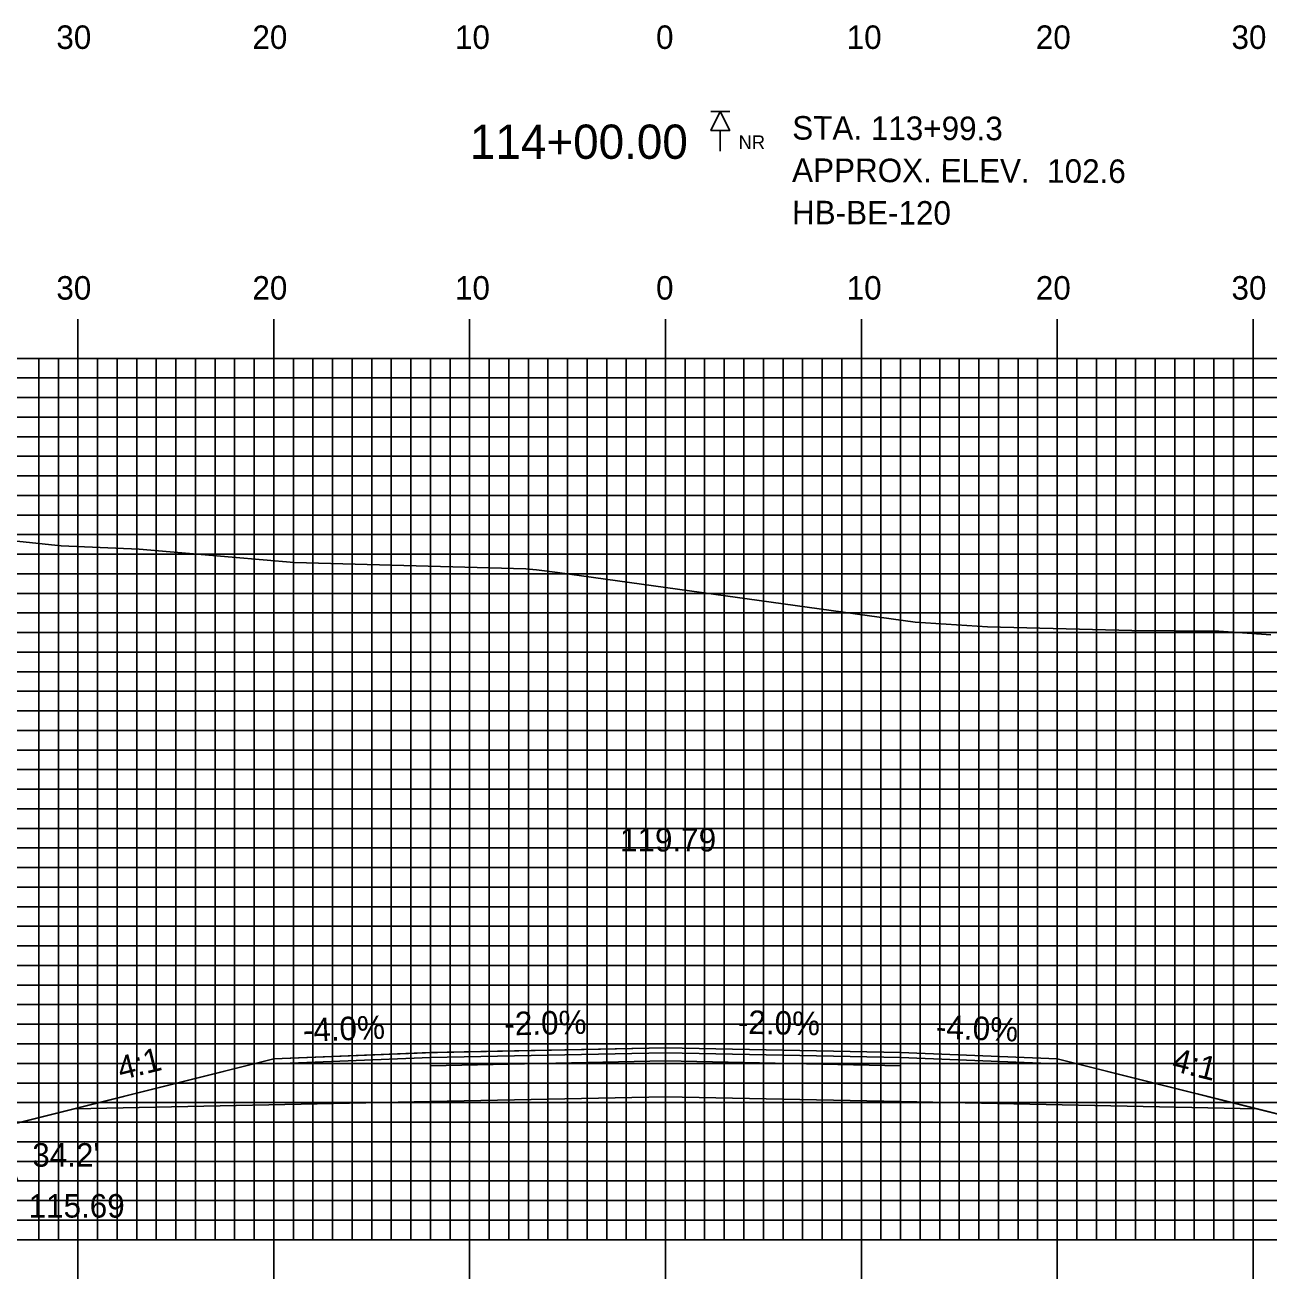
# Model space of a CAD drawing. Extents: x 1770448 to 1770792, y 442591 to 442811.
# Drawn here: x 1770581.3 to 1770644.9, y 442676.7 to 442740.7 of the extents above; entities that cross this region are included whole.
import ezdxf

# ---------------------------------------------------------------- set-up
doc = ezdxf.new("R2010")
doc.units = 0
for name, color, linetype in [('ANNOTATION', 7, 'Continuous'), ('BORING - NO REFUSAL', 7, 'Continuous'), ('D_Roadway_Centerline', 7, 'Continuous'), ('D_Roadway_Centerline_Text', 7, 'Continuous'), ('D_Roadway_Edge_Shoulder', 7, 'Continuous'), ('D_Roadway_Edge_TW', 7, 'Continuous'), ('D_Roadway_Pavement', 7, 'Continuous'), ('D_Roadway_SlopeLines', 7, 'Continuous'), ('D_Roadway_SubGrade', 7, 'Continuous'), ('H_V ANNOTATION', 7, 'Continuous'), ('MAJOR', 7, 'Continuous'), ('MINOR', 7, 'Continuous'), ('S_Roadway_Centerline', 7, 'Continuous')]:
    doc.layers.add(name, color=color, linetype=linetype)

msp = doc.modelspace()

# ---------------------------------------------------------------- linework, layer by layer
at = {"layer": 'ANNOTATION'}
msp.add_lwpolyline([(1770586.666, 442681.667), (1770580.975, 442681.667), (1770579.867, 442684.352)], dxfattribs=at)
at = {"layer": 'BORING - NO REFUSAL'}
for p, q in [((1770617.321, 442736.265), (1770616.361, 442736.265)), ((1770616.841, 442735.306), (1770616.841, 442734.247))]:
    msp.add_line(p, q, dxfattribs=at)
msp.add_lwpolyline([(1770616.841, 442736.265), (1770617.321, 442735.306), (1770616.361, 442735.306)], close=True, dxfattribs=at)
at = {"layer": 'D_Roadway_Centerline'}
msp.add_lwpolyline([(1770520.231, 442717.147), (1770521.481, 442716.994), (1770522.731, 442716.681), (1770523.265, 442716.479), (1770523.981, 442716.207), (1770524.335, 442716.028), (1770525.231, 442715.573), (1770525.235, 442715.571), (1770556.94, 442697.453), (1770579.859, 442684.357), (1770579.867, 442684.352), (1770581.355, 442684.724), (1770583.867, 442685.352), (1770594.041, 442687.896), (1770601.792, 442688.206), (1770602.042, 442688.216), (1770602.398, 442688.223), (1770614.042, 442688.456), (1770626.042, 442688.216), (1770634.041, 442687.896), (1770644.215, 442685.352), (1770646.624, 442684.75)], dxfattribs=at)
at = {"layer": 'D_Roadway_Edge_Shoulder'}
for points in [[(1770602.042, 442688.216), (1770594.041, 442687.896), (1770594.041, 442687.646), (1770602.042, 442687.966)], [(1770626.042, 442688.216), (1770634.041, 442687.896), (1770634.041, 442687.646), (1770626.042, 442687.966)]]:
    msp.add_lwpolyline(points, close=True, dxfattribs=at)
at = {"layer": 'D_Roadway_Edge_TW'}
msp.add_lwpolyline([(1770602.042, 442687.966), (1770602.042, 442688.216), (1770614.042, 442688.456), (1770626.042, 442688.216), (1770626.042, 442687.966), (1770614.042, 442688.206)], close=True, dxfattribs=at)
at = {"layer": 'D_Roadway_Pavement'}
msp.add_lwpolyline([(1770602.042, 442687.549), (1770602.042, 442687.966), (1770614.042, 442688.206), (1770626.042, 442687.966), (1770626.042, 442687.549), (1770614.042, 442687.789)], close=True, dxfattribs=at)
at = {"layer": 'D_Roadway_SlopeLines'}
for points in [[(1770594.041, 442687.896), (1770579.867, 442684.352)], [(1770634.041, 442687.896), (1770648.215, 442684.352)]]:
    msp.add_lwpolyline(points, dxfattribs=at)
at = {"layer": 'D_Roadway_SubGrade'}
msp.add_lwpolyline([(1770602.042, 442685.716), (1770583.867, 442685.352), (1770594.041, 442687.896), (1770594.041, 442687.646), (1770602.042, 442687.966), (1770614.042, 442688.206), (1770626.042, 442687.966), (1770634.041, 442687.646), (1770634.041, 442687.896), (1770644.215, 442685.352), (1770626.042, 442685.716), (1770614.042, 442685.956)], close=True, dxfattribs=at)
at = {"layer": 'MAJOR'}
for p, q in [((1770584.041, 442725.669), (1770584.041, 442723.665)), ((1770594.041, 442725.669), (1770594.041, 442723.665)), ((1770604.041, 442725.669), (1770604.041, 442723.665)), ((1770614.041, 442725.669), (1770614.041, 442723.665)), ((1770624.041, 442725.669), (1770624.041, 442723.665)), ((1770634.041, 442725.669), (1770634.041, 442723.665)), ((1770644.041, 442725.669), (1770644.041, 442723.665)), ((1770474.041, 442723.665), (1770754.041, 442723.665)), ((1770474.041, 442723.665), (1770754.041, 442723.665)), ((1770584.041, 442678.665), (1770584.041, 442723.665)), ((1770594.041, 442678.665), (1770594.041, 442723.665)), ((1770604.041, 442678.665), (1770604.041, 442723.665)), ((1770614.041, 442678.665), (1770614.041, 442723.665)), ((1770624.041, 442678.665), (1770624.041, 442723.665)), ((1770634.041, 442678.665), (1770634.041, 442723.665)), ((1770644.041, 442678.665), (1770644.041, 442723.665)), ((1770474.041, 442718.665), (1770754.041, 442718.665)), ((1770474.041, 442713.665), (1770754.041, 442713.665)), ((1770474.041, 442708.665), (1770754.041, 442708.665)), ((1770474.041, 442703.665), (1770754.041, 442703.665)), ((1770474.041, 442698.665), (1770754.041, 442698.665)), ((1770474.041, 442693.665), (1770754.041, 442693.665)), ((1770474.041, 442688.665), (1770754.041, 442688.665)), ((1770474.041, 442683.665), (1770754.041, 442683.665)), ((1770474.041, 442678.665), (1770754.041, 442678.665)), ((1770474.041, 442678.665), (1770754.041, 442678.665)), ((1770584.041, 442676.661), (1770584.041, 442678.665)), ((1770594.041, 442676.661), (1770594.041, 442678.665)), ((1770604.041, 442676.661), (1770604.041, 442678.665)), ((1770614.041, 442676.661), (1770614.041, 442678.665)), ((1770624.041, 442676.661), (1770624.041, 442678.665)), ((1770634.041, 442676.661), (1770634.041, 442678.665)), ((1770644.041, 442676.661), (1770644.041, 442678.665))]:
    msp.add_line(p, q, dxfattribs=at)
at = {"layer": 'MINOR'}
for p, q in [((1770582.041, 442678.665), (1770582.041, 442723.665)), ((1770583.041, 442678.665), (1770583.041, 442723.665)), ((1770585.041, 442678.665), (1770585.041, 442723.665)), ((1770586.041, 442678.665), (1770586.041, 442723.665)), ((1770587.041, 442678.665), (1770587.041, 442723.665)), ((1770588.041, 442678.665), (1770588.041, 442723.665)), ((1770589.041, 442678.665), (1770589.041, 442723.665)), ((1770590.041, 442678.665), (1770590.041, 442723.665)), ((1770591.041, 442678.665), (1770591.041, 442723.665)), ((1770592.041, 442678.665), (1770592.041, 442723.665)), ((1770593.041, 442678.665), (1770593.041, 442723.665)), ((1770595.041, 442678.665), (1770595.041, 442723.665)), ((1770596.041, 442678.665), (1770596.041, 442723.665)), ((1770597.041, 442678.665), (1770597.041, 442723.665)), ((1770598.041, 442678.665), (1770598.041, 442723.665)), ((1770599.041, 442678.665), (1770599.041, 442723.665)), ((1770600.041, 442678.665), (1770600.041, 442723.665)), ((1770601.041, 442678.665), (1770601.041, 442723.665)), ((1770602.041, 442678.665), (1770602.041, 442723.665)), ((1770603.041, 442678.665), (1770603.041, 442723.665)), ((1770605.041, 442678.665), (1770605.041, 442723.665)), ((1770606.041, 442678.665), (1770606.041, 442723.665)), ((1770607.041, 442678.665), (1770607.041, 442723.665)), ((1770608.041, 442678.665), (1770608.041, 442723.665)), ((1770609.041, 442678.665), (1770609.041, 442723.665)), ((1770610.041, 442678.665), (1770610.041, 442723.665)), ((1770611.041, 442678.665), (1770611.041, 442723.665)), ((1770612.041, 442678.665), (1770612.041, 442723.665)), ((1770613.041, 442678.665), (1770613.041, 442723.665)), ((1770615.041, 442678.665), (1770615.041, 442723.665)), ((1770616.041, 442678.665), (1770616.041, 442723.665)), ((1770617.041, 442678.665), (1770617.041, 442723.665)), ((1770618.041, 442678.665), (1770618.041, 442723.665)), ((1770619.041, 442678.665), (1770619.041, 442723.665)), ((1770620.041, 442678.665), (1770620.041, 442723.665)), ((1770621.041, 442678.665), (1770621.041, 442723.665)), ((1770622.041, 442678.665), (1770622.041, 442723.665)), ((1770623.041, 442678.665), (1770623.041, 442723.665)), ((1770625.041, 442678.665), (1770625.041, 442723.665)), ((1770626.041, 442678.665), (1770626.041, 442723.665)), ((1770627.041, 442678.665), (1770627.041, 442723.665)), ((1770628.041, 442678.665), (1770628.041, 442723.665)), ((1770629.041, 442678.665), (1770629.041, 442723.665)), ((1770630.041, 442678.665), (1770630.041, 442723.665)), ((1770631.041, 442678.665), (1770631.041, 442723.665)), ((1770632.041, 442678.665), (1770632.041, 442723.665)), ((1770633.041, 442678.665), (1770633.041, 442723.665)), ((1770635.041, 442678.665), (1770635.041, 442723.665)), ((1770636.041, 442678.665), (1770636.041, 442723.665)), ((1770637.041, 442678.665), (1770637.041, 442723.665)), ((1770638.041, 442678.665), (1770638.041, 442723.665)), ((1770639.041, 442678.665), (1770639.041, 442723.665)), ((1770640.041, 442678.665), (1770640.041, 442723.665)), ((1770641.041, 442678.665), (1770641.041, 442723.665)), ((1770642.041, 442678.665), (1770642.041, 442723.665)), ((1770643.041, 442678.665), (1770643.041, 442723.665)), ((1770474.041, 442722.665), (1770754.041, 442722.665)), ((1770474.041, 442721.665), (1770754.041, 442721.665)), ((1770474.041, 442720.665), (1770754.041, 442720.665)), ((1770474.041, 442719.665), (1770754.041, 442719.665)), ((1770474.041, 442717.665), (1770754.041, 442717.665)), ((1770474.041, 442716.665), (1770754.041, 442716.665)), ((1770474.041, 442715.665), (1770754.041, 442715.665)), ((1770474.041, 442714.665), (1770754.041, 442714.665)), ((1770474.041, 442712.665), (1770754.041, 442712.665)), ((1770474.041, 442711.665), (1770754.041, 442711.665)), ((1770474.041, 442710.665), (1770754.041, 442710.665)), ((1770474.041, 442709.665), (1770754.041, 442709.665)), ((1770474.041, 442707.665), (1770754.041, 442707.665)), ((1770474.041, 442706.665), (1770754.041, 442706.665)), ((1770474.041, 442705.665), (1770754.041, 442705.665)), ((1770474.041, 442704.665), (1770754.041, 442704.665)), ((1770474.041, 442702.665), (1770754.041, 442702.665)), ((1770474.041, 442701.665), (1770754.041, 442701.665)), ((1770474.041, 442700.665), (1770754.041, 442700.665)), ((1770474.041, 442699.665), (1770754.041, 442699.665)), ((1770474.041, 442697.665), (1770754.041, 442697.665)), ((1770474.041, 442696.665), (1770754.041, 442696.665)), ((1770474.041, 442695.665), (1770754.041, 442695.665)), ((1770474.041, 442694.665), (1770754.041, 442694.665)), ((1770474.041, 442692.665), (1770754.041, 442692.665)), ((1770474.041, 442691.665), (1770754.041, 442691.665)), ((1770474.041, 442690.665), (1770754.041, 442690.665)), ((1770474.041, 442689.665), (1770754.041, 442689.665)), ((1770474.041, 442687.665), (1770754.041, 442687.665)), ((1770474.041, 442686.665), (1770754.041, 442686.665)), ((1770474.041, 442685.665), (1770754.041, 442685.665)), ((1770474.041, 442684.665), (1770754.041, 442684.665)), ((1770474.041, 442682.665), (1770754.041, 442682.665)), ((1770474.041, 442681.665), (1770754.041, 442681.665)), ((1770474.041, 442680.665), (1770754.041, 442680.665)), ((1770474.041, 442679.665), (1770754.041, 442679.665))]:
    msp.add_line(p, q, dxfattribs=at)
at = {"layer": 'S_Roadway_Centerline'}
msp.add_lwpolyline([(1770515.443, 442717.427), (1770522.915, 442716.991), (1770527.536, 442716.729), (1770535.901, 442716.632), (1770546.593, 442716.254), (1770547.364, 442716.236), (1770559.275, 442715.778), (1770567.209, 442715.603), (1770577.33, 442714.702), (1770583.185, 442714.096), (1770587.164, 442713.929), (1770595.084, 442713.245), (1770606.917, 442712.912), (1770607.453, 442712.868), (1770608.527, 442712.725), (1770626.794, 442710.192), (1770630.475, 442709.961), (1770637.856, 442709.774), (1770642.286, 442709.739), (1770644.945, 442709.555)], dxfattribs=at)

# ---------------------------------------------------------------- texts
at = {"layer": 'ANNOTATION'}
for s, rotation, p in [('-2.0%', 1.14577, (1770605.826, 442689.092)), ('-2.0%', 358.85423, (1770617.728, 442689.183)), ('-4.0%', 2.29037, (1770595.548, 442688.758)), ('-4.0%', 357.70924, (1770627.833, 442688.946)), ('4:1', 14.03874, (1770586.234, 442686.806)), ('4:1', 345.9616, (1770639.838, 442687.308))]:
    msp.add_text(s, height=1.2, rotation=rotation, dxfattribs=at).set_placement(p)
for s, p in [("34.2'", (1770581.709, 442682.393)), ('115.69', (1770581.522, 442679.793))]:
    msp.add_text(s, height=1.2, dxfattribs=at).set_placement(p)
at = {"layer": 'BORING - NO REFUSAL'}
for s, p in [('STA. 113+99.3', (1770620.511, 442734.837)), ('APPROX. ELEV.  102.6', (1770620.504, 442732.677)), ('HB-BE-120', (1770620.497, 442730.517))]:
    msp.add_text(s, height=1.2, rotation=359.81416, dxfattribs=at).set_placement(p)
msp.add_text('NR', height=0.6998, dxfattribs=at).set_placement((1770617.774, 442734.35))
at = {"layer": 'D_Roadway_Centerline'}
for s, p in [('C', (1770614.036, 442688.456)), ('L', (1770614.042, 442688.449))]:
    msp.add_text(s, height=0.0146, dxfattribs=at).set_placement(p)
at = {"layer": 'D_Roadway_Centerline_Text'}
msp.add_text('119.79', height=1.2, dxfattribs=at).set_placement((1770611.719, 442698.486))
at = {"layer": 'H_V ANNOTATION'}
for s, height, p in [('30', 1.2, (1770582.939, 442739.465)), ('20', 1.2, (1770592.949, 442739.465)), ('10', 1.2, (1770603.292, 442739.465)), ('0', 1.2, (1770613.559, 442739.465)), ('10', 1.2, (1770623.292, 442739.465)), ('20', 1.2, (1770632.949, 442739.465)), ('30', 1.2, (1770642.939, 442739.465)), ('114+00.00', 1.75, (1770604.055, 442733.853)), ('30', 1.2, (1770582.939, 442726.665)), ('20', 1.2, (1770592.949, 442726.665)), ('10', 1.2, (1770603.292, 442726.665)), ('0', 1.2, (1770613.559, 442726.665)), ('10', 1.2, (1770623.292, 442726.665)), ('20', 1.2, (1770632.949, 442726.665)), ('30', 1.2, (1770642.939, 442726.665))]:
    msp.add_text(s, height=height, dxfattribs=at).set_placement(p)

doc.saveas('drawing.dxf')
